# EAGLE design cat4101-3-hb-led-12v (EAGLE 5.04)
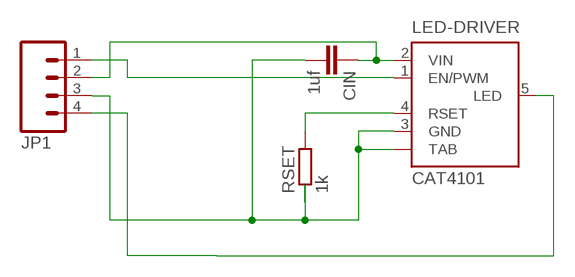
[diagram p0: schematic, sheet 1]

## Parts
CIN  1uf  C-EUC1206  [C1206]
JP1  M04PTH  [1X04]
LED-DRIVER  CAT4101  [TO263_5]
RSET  1k  R-EU_R1210  [R1210]

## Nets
N$1: CIN.1 JP1.2 LED-DRIVER.2(VIN)
N$3: JP1.1 LED-DRIVER.1(EN/PWM)
N$4: JP1.4 LED-DRIVER.5(LED)
N$6: CIN.2 JP1.3 LED-DRIVER.3(GND) LED-DRIVER.TAB RSET.1
N$7: LED-DRIVER.4(RSET) RSET.2

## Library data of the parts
CIN = rcl:C-EU: CAPACITOR, European symbol
JP1 = SparkFun:M04: Header 4 Standard 4-pin 0.1" header. Use with straight break away headers (SKU : PRT-00116), right angle break away headers (PRT-00553), swiss pins (PRT-00743), machine pins (PRT-00117), and female headers (PRT-00115). Molex polarized connector foot print use with SKU : PRT-08231 with associated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
LED-DRIVER = on-semiconductor:CAT4101: 1A Constant-Current LED Driver with PWM Dimming Source: ON Semiconductor .. 4101.pdf
RSET = resistor:R-EU_: RESISTOR, European symbol

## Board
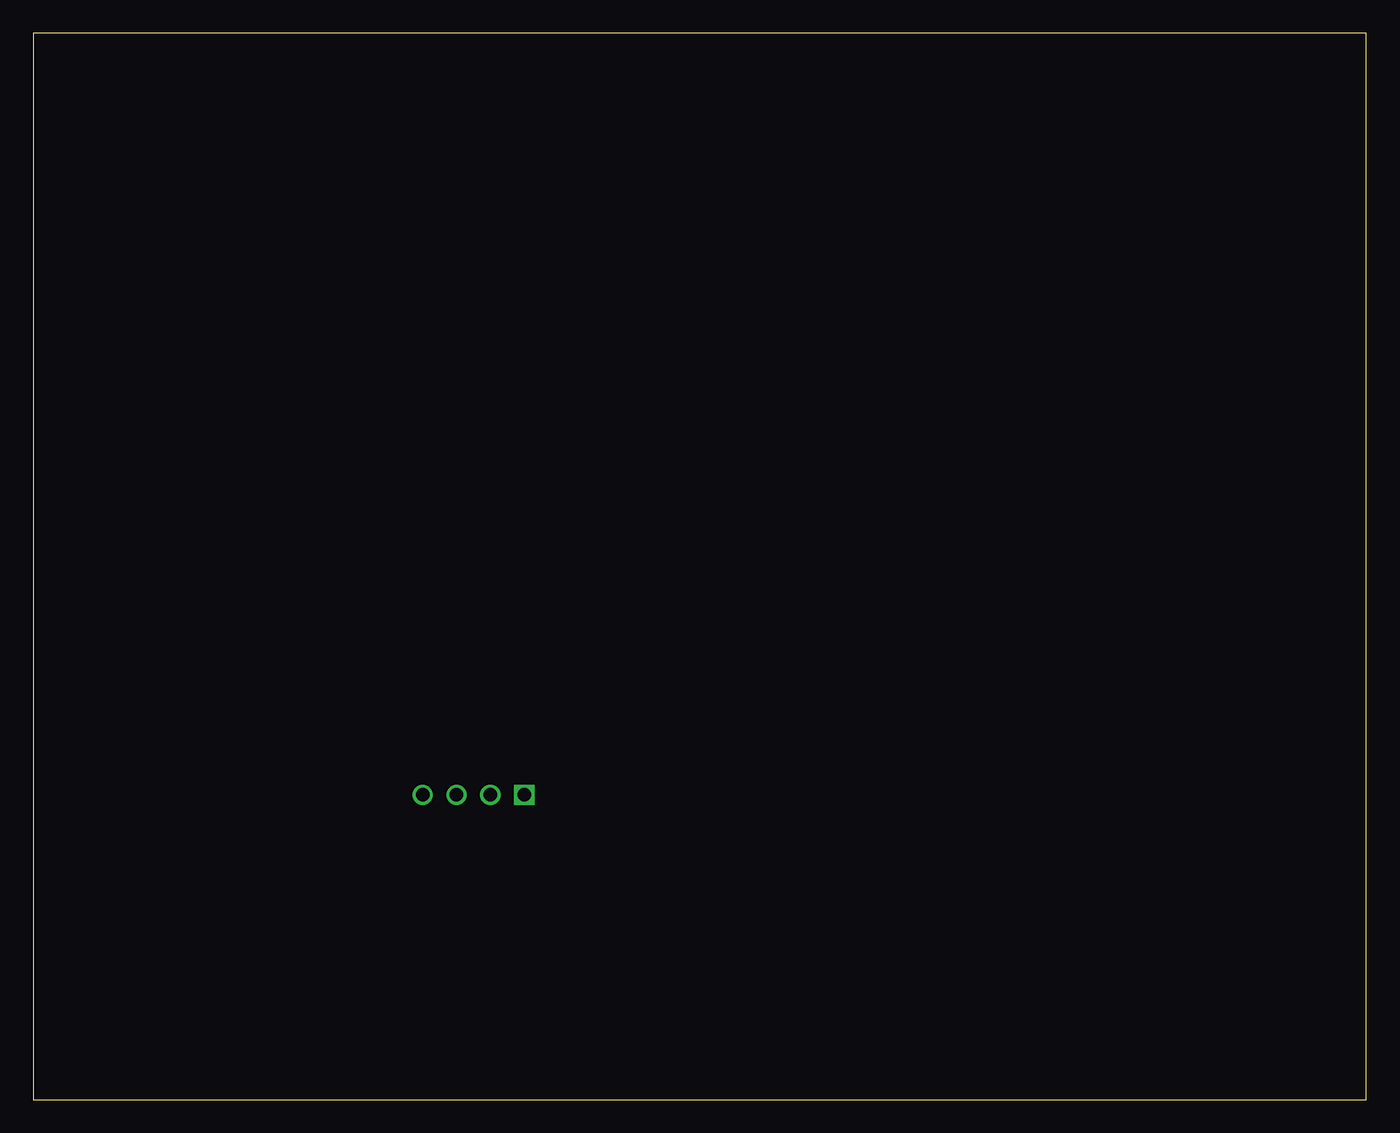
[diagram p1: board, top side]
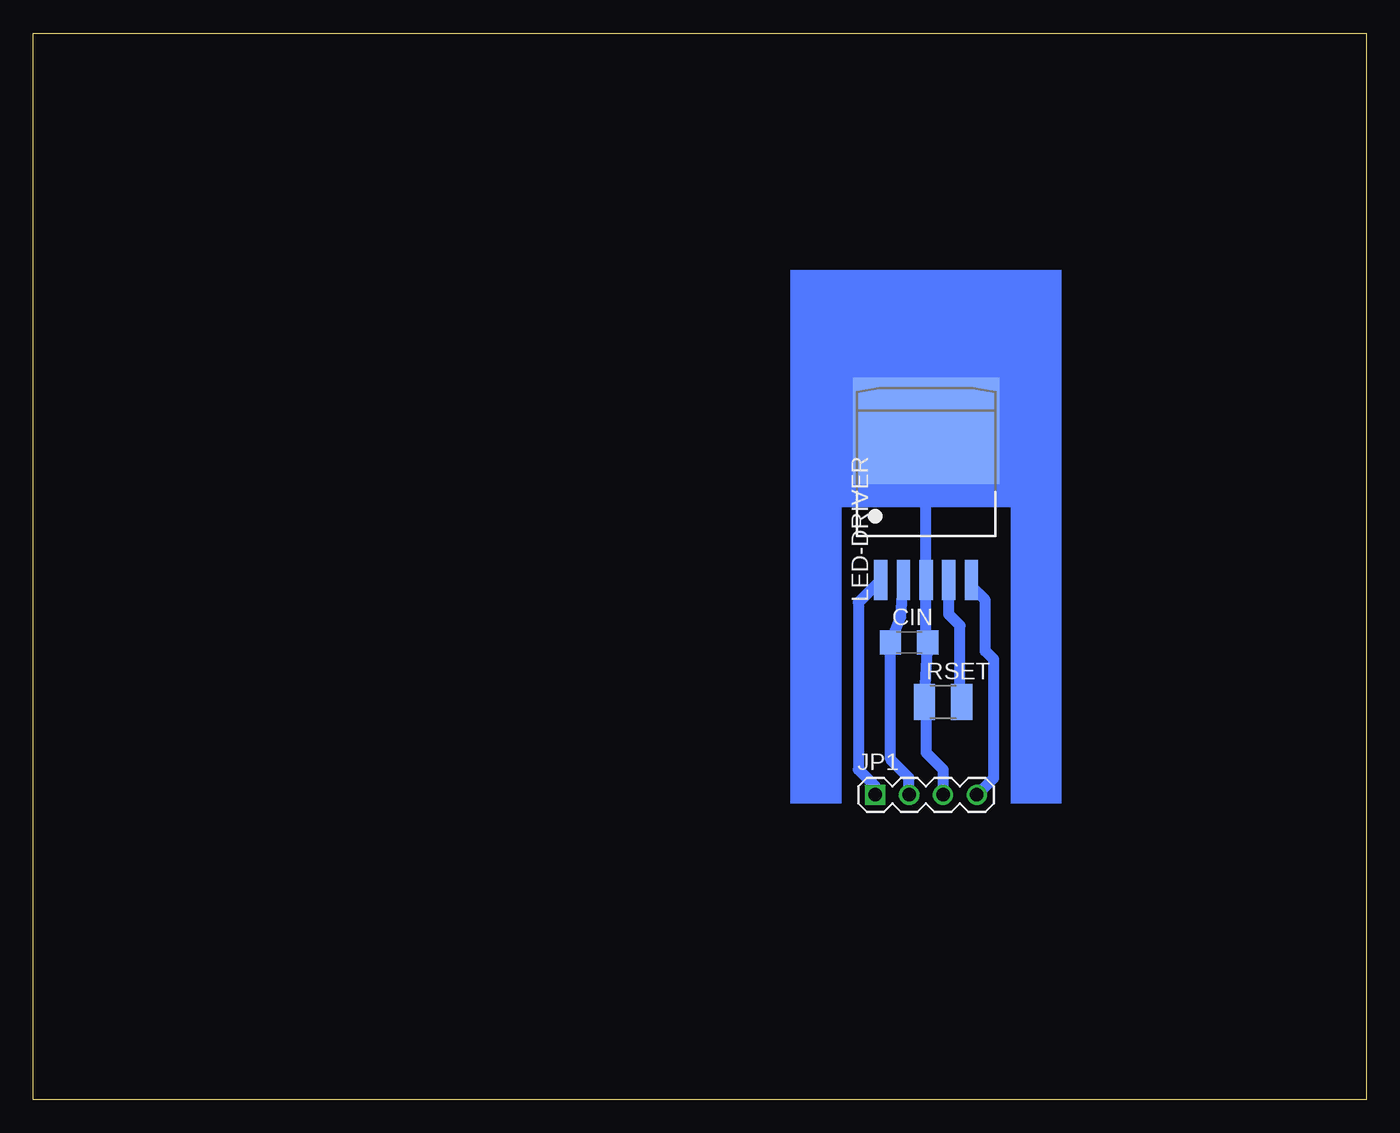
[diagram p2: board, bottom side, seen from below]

Size 100 x 80 mm. Coordinates in mm from the lower left corner, seen from the top.
Outline: 0,0 100,0 100,80 0,80 0,0
Copper layers (1*16): Top 0.035mm / dielectric 1.5mm / Bottom 0.035mm
Design rules "default": minimum track width 10mil, minimum drill 24mil, track to track 8mil, track to pad 8mil, pad to pad 8mil, via to via 8mil, smd to smd 8mil, copper to edge 40mil, drill to drill 8mil, minimum pad ring 10mil, minimum via ring 8mil, stop-mask expansion 4mil, vias tented up to drill 0mil, thermal gap 10mil

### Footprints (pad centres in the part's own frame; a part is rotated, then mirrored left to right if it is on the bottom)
C1206 = smd 1.6 x 1.8: 1 -1.4,0; 2 1.4,0
1X04 = drill 1.016 square: 1 0,0 | drill 1.016 round: 2 2.54,0; 3 5.08,0; 4 7.62,0
TO263_5 = smd 1 x 3: 1 -3.4,-8; 2 -1.7,-8; 3 0,-8; 4 1.7,-8; 5 3.4,-8 | smd 11 x 8: TAB 0,3.175
R1210 = smd 1.6 x 2.7: 1 -1.4,0; 2 1.4,0

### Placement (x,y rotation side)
CIN  34.29,34.29 0 bottom
JP1  36.83,22.86 0 bottom
LED-DRIVER  33.02,46.99 0 bottom
RSET  31.75,29.84 0 bottom

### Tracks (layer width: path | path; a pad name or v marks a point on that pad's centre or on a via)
N$1
  Bottom 0.813: LED-DRIVER.2 34.92,36.2 CIN.1 35.69,25.53 34.29,24.13 JP1.2
N$3
  Bottom 0.813: LED-DRIVER.1 38.1,37.31 38.1,24.77 36.83,23.5 JP1.1
N$4
  Bottom 0.813: JP1.4 27.94,24.13 27.94,33.02 28.57,33.66 28.57,37.47 29.62,38.51 LED-DRIVER.5
N$6
  Bottom 0.813: LED-DRIVER.TAB LED-DRIVER.3 33.02,34.42 CIN.2 RSET.1 33.02,29.71 33.02,26.04 31.75,24.77 JP1.3
N$7
  Bottom 0.813: RSET.2 30.48,29.98 30.48,35.56 31.32,36.4 LED-DRIVER.4
(copper drawn outside any net)
  shapes: Bottom area x4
